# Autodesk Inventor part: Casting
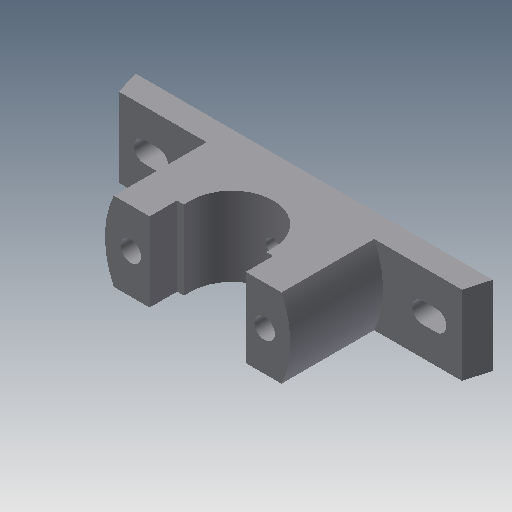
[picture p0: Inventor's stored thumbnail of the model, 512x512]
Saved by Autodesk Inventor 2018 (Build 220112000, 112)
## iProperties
Created: 2009-04
Part Number: Casting
Document SubType Name: Modeling
Designer: Sham
Density: 1 g/cm^3
Material: Generic
Appearance: Default
Author: Sham
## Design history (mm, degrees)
sketch "Sketch1"
  geometry: L1 (-104, 0)-(104, 0); L2 (-104, 0)-(-100, 14); L3 (-100, 14)-(100, 14); L4 (100, 14)-(104, 0); 1 further point
  constraints: 8 end point, 1 horizontal, 1 midpoint, 1 parallel, 1 other
  dimensions: "d0" = 208 distance of L1.start L1.end; "d1" = 104 distance of L1.end point (0, 0); "d2" = 4 horizontal distance of L1.start L2.end; "d3" = 4 horizontal distance of L1.end L3.end; "d10" = 14 distance between parallel lines of L1 L3
extrude "Extrusion1" new body sketch "Sketch1" stored distance "d4" = 46; taper "d5" = 0 deg
sketch "Sketch2"
  geometry: L1 (51.143, 46)-(148.857, 46); L2 (148.857, 0)-(51.143, 0); A1 r 54 centre (100, 23) between (51.143, 46) and (51.143, 0); A2 r 54 centre (100, 23) between (148.857, 0) and (148.857, 46)
  constraints: 4 end point, 4 point on circle, 2 centre point, 1 parallel
extrude "Extrusion2" join sketch "Sketch2" distance "d8" = 54; taper "d9" = 0 deg
sketch "Sketch3"
  geometry: L1 (-28, 68)-(-28, 52); L2 (-28, 52)-(-24, 52); L3 (28, 68)-(28, 52); L4 (28, 52)-(24, 52); L5 (-28, 68)-(28, 68); L6 (-100, 14)-(-48.857, 14) reference; L7 (0, 48)-(0, 19); L8 (48.857, 14)-(100, 14) reference; L9 (48.857, 68)-(-48.857, 68) reference; L10 (-24, 48)-(-24, 52); L11 (24, 48)-(24, 52); A1 r 24 centre (0, 48) between (-24, 48) and (24, 48); 1 further point
  constraints: 16 end point, 5 perpendicular, 2 point on circle, 2 symmetric about line, 1 centre point, 1 tangent, 1 vertical alignment, 1 other
  dimensions: "d11" = 16 distance of L1.start L1.end; "d16" = 24 radius of A1; "d17" = 16 distance of L3.start L3.end; "d52" = 56 distance between parallel lines of L1 L3; "d54" = 54 distance between parallel lines of L8 L9 (derived)
extrude "Extrusion3" cut sketch "Sketch3" distance "d18" = 54; taper "d19" = 0 deg
sketch "Sketch4"
  geometry: L1 (-23, 29)-(-15, 29); L2 (-15, 17)-(-23, 17); L3 (-185, 29)-(-177, 29); L4 (-177, 17)-(-185, 17); A1 r 6 centre (-15, 23) between (-15, 17) and (-15, 29); A2 r 6 centre (-23, 23) between (-23, 29) and (-23, 17); A3 r 6 centre (-177, 23) between (-177, 17) and (-177, 29); A4 r 6 centre (-185, 23) between (-185, 29) and (-185, 17)
  constraints: 8 end point, 8 point on circle, 8 tangent, 4 centre point, 3 parallel
  dimensions: "d20" = 8 distance of A1.centre A2.centre; "d21" = 6 radius of A1; "d24" = 6 radius of A3; "d25" = 8 distance of A4.centre A3.centre
extrude "Extrusion4" cut sketch "Sketch4" distance "d28" = 54; taper "d29" = 0 deg
sketch "Sketch5"
  geometry: L1 (208, 0)-(0, 0) reference; L2 (52, -10)-(78, -10); L3 (78, -10)-(78, -36); L4 (78, -36)-(52, -36); L5 (52, -36)-(52, -10); L6 (130, -10)-(156, -10); L7 (156, -10)-(156, -36); L8 (156, -36)-(130, -36); L9 (130, -36)-(130, -10); L10 (0, -46)-(208, -46) reference; L11 (104, -23)-(104, -46)
  constraints: 18 end point, 5 perpendicular, 4 parallel, 2 horizontal, 1 midpoint
  dimensions: "d30" = 26 distance of L2.start L2.end; "d31" = 10 distance between parallel lines of L2 L1; "d32" = 10 distance between parallel lines of L1 L6; "d65" = 26 distance between parallel lines of L3 L11; "d66" = 26 distance between parallel lines of L9 L11
extrude "Extrusion5" cut sketch "Sketch5" distance "d34" = 10; taper "d35" = 0 deg
sketch "Sketch6"
  geometry: L1 (148.857, 0)-(128, 0) reference; L2 (72, 0)-(51.143, 0) reference; L3 (0, 46)-(0, 0) reference; L4 (200, 46)-(200, 0) reference; C1 r 6 at (61, 23); C2 r 6 at (139, 23); 1 further point
  constraints: 2 centre point, 1 equal radius
  dimensions: "d36" = 12 diameter of C1; "d37" = 78 distance of C2.centre C1.centre; "d39" = 39 distance of C2.centre point (100, 23); "d58" = 39 distance of C1.centre point (100, 23); "d59" = 23 distance from line of L1 C2.centre; "d60" = 23 distance from line of L2 C1.centre; "d61" = 61 distance from line of L3 C1.centre; "d62" = 61 distance from line of L4 C2.centre (derived)
extrude "Extrusion6" cut sketch "Sketch6" extent not by distance; stored distance "d40" = 10; taper "d41" = 0 deg
workplane "Work Plane1"
sketch "Sketch7"
  geometry: L1 (-4, 46)-(204, 46) reference; L2 (-4, 0)-(-4, 46) reference; 1 further point
  dimensions: "d43" = 23 distance from line of L1 point (100, 23); "d44" = 104 distance from line of point (100, 23) L2
hole "Hole1" sketch "Sketch7" at (100, 23) diameter "d45" = 8; stored, may be unused: countersink angle "d49" = 90 deg, drill point angle "d51" = 118 deg; dims "d46" = 6, "d47" = 8, "d48" = 16, "d50" = 8
body "Solid1"
other parameters: "d6" = 108, "d42" = -52
